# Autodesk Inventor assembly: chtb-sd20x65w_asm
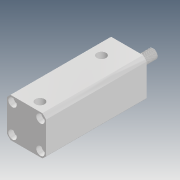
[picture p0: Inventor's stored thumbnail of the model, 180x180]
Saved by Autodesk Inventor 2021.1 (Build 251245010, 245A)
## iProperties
Company: Microsoft
Created: 2018-05
Part Number: chtb-sd20x65w_asm
Description: STEP AP214
Document SubType Name: Assembly
Designer: user
Title: chtb-sd20x65w_asm.STEP
Author: Windows
Revision Number: ÈÎºÎ
Sending System: SolidWorks 2015
Preprocessor: SwSTEP 2.0
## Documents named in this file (4)
- D:\Vault_2016\Projekty\Clamptek\Hydraulic\CHTB\CHTB-20\Inventor\CHTB-SD20x65W\chtb-sd20x65w_asm.iam
- D:\Vault_2016\Projekty\Clamptek\Hydraulic\CHTB\CHTB-20\Inventor\CHTB-SD20x65W\CHTB-SD20X65NBT.ipt
- D:\Vault_2016\Projekty\Clamptek\Hydraulic\CHTB\CHTB-20\Inventor\CHTB-SD20x65W\CHTB-SD20X65WHSG.ipt
- D:\Vault_2016\Projekty\Clamptek\Hydraulic\CHTB\CHTB-20\Inventor\CHTB-SD20x65W\QG.ipt
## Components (3 placed, 3 different names)
1. CHTB-SD20X65NBT_1
2. CHTB-SD20X65WHSG_2
3. QG_3
